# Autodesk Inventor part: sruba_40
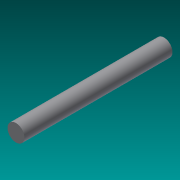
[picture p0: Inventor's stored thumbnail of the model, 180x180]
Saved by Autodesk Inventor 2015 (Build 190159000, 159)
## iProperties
Created: 2016-02
Part Number: sruba_40
Material: Generic
Document SubType Name: Modeling
Designer: Rafał
Density: 1 g/cm^3
Appearance: Default
Author: Rafał
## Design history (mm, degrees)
sketch "Sketch1"
  geometry: C1 r 2 at (0, 0); 1 further point
  constraints: 1 centre point, 1 coincident
  dimensions: "d0" = 4 diameter of C1
extrude "Extrusion1" new body sketch "Sketch1" distance "d1" = 35; taper "d2" = 0 deg
body "Solid1"
